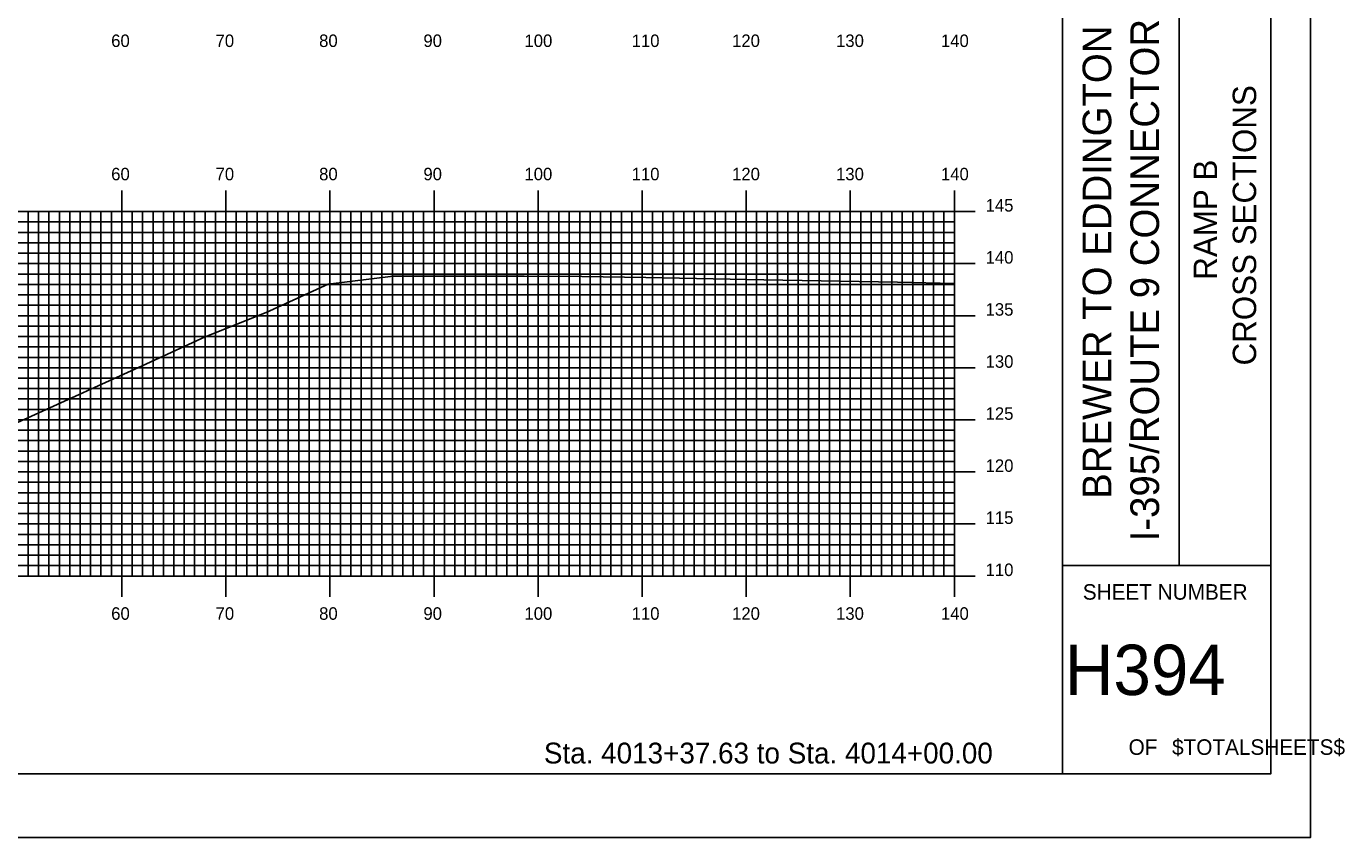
# Model space of a CAD drawing. Extents: x 853328 to 853671, y 364661 to 364881.
# Drawn here: x 853544.1 to 853670.8, y 364661.3 to 364739.1 of the extents above; entities that cross this region are included whole.
import ezdxf

# ---------------------------------------------------------------- set-up
doc = ezdxf.new("R2010")
doc.units = 0
for name, color, linetype in [('BORDER', 7, 'Continuous'), ('H_V ANNOTATION', 7, 'Continuous'), ('MAJOR', 7, 'Continuous'), ('MINOR', 7, 'Continuous'), ('PLOT BOUNDARY', 7, 'Continuous'), ('S_Roadway_Centerline', 7, 'Continuous')]:
    doc.layers.add(name, color=color, linetype=linetype)

msp = doc.modelspace()

# ---------------------------------------------------------------- linework, layer by layer
at = {"layer": 'BORDER'}
for p, q in [((853643.69, 364667.37), (853643.69, 364877.37)), ((853654.88, 364687.38), (853654.88, 364757.38)), ((853643.69, 364687.38), (853663.69, 364687.38))]:
    msp.add_line(p, q, dxfattribs=at)
msp.add_lwpolyline([(853343.69, 364667.37), (853663.69, 364667.37), (853663.69, 364877.37), (853343.69, 364877.37)], close=True, dxfattribs=at)
at = {"layer": 'MAJOR'}
for p, q in [((853553.29, 364723.38), (853553.29, 364721.37)), ((853563.29, 364723.38), (853563.29, 364721.37)), ((853573.29, 364723.38), (853573.29, 364721.37)), ((853583.29, 364723.38), (853583.29, 364721.37)), ((853593.29, 364723.38), (853593.29, 364721.37)), ((853603.29, 364723.38), (853603.29, 364721.37)), ((853613.29, 364723.38), (853613.29, 364721.37)), ((853623.29, 364723.38), (853623.29, 364721.37)), ((853633.29, 364723.38), (853633.29, 364721.37)), ((853353.29, 364721.37), (853633.29, 364721.37)), ((853353.29, 364721.37), (853633.29, 364721.37)), ((853553.29, 364686.37), (853553.29, 364721.37)), ((853563.29, 364686.37), (853563.29, 364721.37)), ((853573.29, 364686.37), (853573.29, 364721.37)), ((853583.29, 364686.37), (853583.29, 364721.37)), ((853593.29, 364686.37), (853593.29, 364721.37)), ((853603.29, 364686.37), (853603.29, 364721.37)), ((853613.29, 364686.37), (853613.29, 364721.37)), ((853623.29, 364686.37), (853623.29, 364721.37)), ((853635.3, 364721.37), (853631.29, 364721.37)), ((853633.29, 364686.37), (853633.29, 364721.37)), ((853633.29, 364686.37), (853633.29, 364721.37)), ((853353.29, 364716.37), (853633.29, 364716.37)), ((853635.3, 364716.37), (853631.29, 364716.37)), ((853353.29, 364711.37), (853633.29, 364711.37)), ((853635.3, 364711.37), (853631.29, 364711.37)), ((853353.29, 364706.37), (853633.29, 364706.37)), ((853635.3, 364706.37), (853631.29, 364706.37)), ((853353.29, 364701.37), (853633.29, 364701.37)), ((853635.3, 364701.37), (853631.29, 364701.37)), ((853353.29, 364696.37), (853633.29, 364696.37)), ((853635.3, 364696.37), (853631.29, 364696.37)), ((853353.29, 364691.37), (853633.29, 364691.37)), ((853635.3, 364691.37), (853631.29, 364691.37)), ((853353.29, 364686.37), (853633.29, 364686.37)), ((853353.29, 364686.37), (853633.29, 364686.37)), ((853553.29, 364684.37), (853553.29, 364686.37)), ((853563.29, 364684.37), (853563.29, 364686.37)), ((853573.29, 364684.37), (853573.29, 364686.37)), ((853583.29, 364684.37), (853583.29, 364686.37)), ((853593.29, 364684.37), (853593.29, 364686.37)), ((853603.29, 364684.37), (853603.29, 364686.37)), ((853613.29, 364684.37), (853613.29, 364686.37)), ((853623.29, 364684.37), (853623.29, 364686.37)), ((853635.3, 364686.37), (853631.29, 364686.37)), ((853633.29, 364684.37), (853633.29, 364686.37))]:
    msp.add_line(p, q, dxfattribs=at)
at = {"layer": 'MINOR'}
for p, q in [((853544.29, 364686.37), (853544.29, 364721.37)), ((853545.29, 364686.37), (853545.29, 364721.37)), ((853546.29, 364686.37), (853546.29, 364721.37)), ((853547.29, 364686.37), (853547.29, 364721.37)), ((853548.29, 364686.37), (853548.29, 364721.37)), ((853549.29, 364686.37), (853549.29, 364721.37)), ((853550.29, 364686.37), (853550.29, 364721.37)), ((853551.29, 364686.37), (853551.29, 364721.37)), ((853552.29, 364686.37), (853552.29, 364721.37)), ((853554.29, 364686.37), (853554.29, 364721.37)), ((853555.29, 364686.37), (853555.29, 364721.37)), ((853556.29, 364686.37), (853556.29, 364721.37)), ((853557.29, 364686.37), (853557.29, 364721.37)), ((853558.29, 364686.37), (853558.29, 364721.37)), ((853559.29, 364686.37), (853559.29, 364721.37)), ((853560.29, 364686.37), (853560.29, 364721.37)), ((853561.29, 364686.37), (853561.29, 364721.37)), ((853562.29, 364686.37), (853562.29, 364721.37)), ((853564.29, 364686.37), (853564.29, 364721.37)), ((853565.29, 364686.37), (853565.29, 364721.37)), ((853566.29, 364686.37), (853566.29, 364721.37)), ((853567.29, 364686.37), (853567.29, 364721.37)), ((853568.29, 364686.37), (853568.29, 364721.37)), ((853569.29, 364686.37), (853569.29, 364721.37)), ((853570.29, 364686.37), (853570.29, 364721.37)), ((853571.29, 364686.37), (853571.29, 364721.37)), ((853572.29, 364686.37), (853572.29, 364721.37)), ((853574.29, 364686.37), (853574.29, 364721.37)), ((853575.29, 364686.37), (853575.29, 364721.37)), ((853576.29, 364686.37), (853576.29, 364721.37)), ((853577.29, 364686.37), (853577.29, 364721.37)), ((853578.29, 364686.37), (853578.29, 364721.37)), ((853579.29, 364686.37), (853579.29, 364721.37)), ((853580.29, 364686.37), (853580.29, 364721.37)), ((853581.29, 364686.37), (853581.29, 364721.37)), ((853582.29, 364686.37), (853582.29, 364721.37)), ((853584.29, 364686.37), (853584.29, 364721.37)), ((853585.29, 364686.37), (853585.29, 364721.37)), ((853586.29, 364686.37), (853586.29, 364721.37)), ((853587.29, 364686.37), (853587.29, 364721.37)), ((853588.29, 364686.37), (853588.29, 364721.37)), ((853589.29, 364686.37), (853589.29, 364721.37)), ((853590.29, 364686.37), (853590.29, 364721.37)), ((853591.29, 364686.37), (853591.29, 364721.37)), ((853592.29, 364686.37), (853592.29, 364721.37)), ((853594.29, 364686.37), (853594.29, 364721.37)), ((853595.29, 364686.37), (853595.29, 364721.37)), ((853596.29, 364686.37), (853596.29, 364721.37)), ((853597.29, 364686.37), (853597.29, 364721.37)), ((853598.29, 364686.37), (853598.29, 364721.37)), ((853599.29, 364686.37), (853599.29, 364721.37)), ((853600.29, 364686.37), (853600.29, 364721.37)), ((853601.29, 364686.37), (853601.29, 364721.37)), ((853602.29, 364686.37), (853602.29, 364721.37)), ((853604.29, 364686.37), (853604.29, 364721.37)), ((853605.29, 364686.37), (853605.29, 364721.37)), ((853606.29, 364686.37), (853606.29, 364721.37)), ((853607.29, 364686.37), (853607.29, 364721.37)), ((853608.29, 364686.37), (853608.29, 364721.37)), ((853609.29, 364686.37), (853609.29, 364721.37)), ((853610.29, 364686.37), (853610.29, 364721.37)), ((853611.29, 364686.37), (853611.29, 364721.37)), ((853612.29, 364686.37), (853612.29, 364721.37)), ((853614.29, 364686.37), (853614.29, 364721.37)), ((853615.29, 364686.37), (853615.29, 364721.37)), ((853616.29, 364686.37), (853616.29, 364721.37)), ((853617.29, 364686.37), (853617.29, 364721.37)), ((853618.29, 364686.37), (853618.29, 364721.37)), ((853619.29, 364686.37), (853619.29, 364721.37)), ((853620.29, 364686.37), (853620.29, 364721.37)), ((853621.29, 364686.37), (853621.29, 364721.37)), ((853622.29, 364686.37), (853622.29, 364721.37)), ((853624.29, 364686.37), (853624.29, 364721.37)), ((853625.29, 364686.37), (853625.29, 364721.37)), ((853626.29, 364686.37), (853626.29, 364721.37)), ((853627.29, 364686.37), (853627.29, 364721.37)), ((853628.29, 364686.37), (853628.29, 364721.37)), ((853629.29, 364686.37), (853629.29, 364721.37)), ((853630.29, 364686.37), (853630.29, 364721.37)), ((853631.29, 364686.37), (853631.29, 364721.37)), ((853632.29, 364686.37), (853632.29, 364721.37)), ((853353.29, 364720.37), (853633.29, 364720.37)), ((853353.29, 364719.37), (853633.29, 364719.37)), ((853633.29, 364720.37), (853631.29, 364720.37)), ((853633.29, 364719.37), (853631.29, 364719.37)), ((853353.29, 364718.37), (853633.29, 364718.37)), ((853633.29, 364718.37), (853631.29, 364718.37)), ((853353.29, 364717.37), (853633.29, 364717.37)), ((853633.29, 364717.37), (853631.29, 364717.37)), ((853353.29, 364715.37), (853633.29, 364715.37)), ((853353.29, 364714.37), (853633.29, 364714.37)), ((853633.29, 364715.37), (853631.29, 364715.37)), ((853633.29, 364714.37), (853631.29, 364714.37)), ((853353.29, 364713.37), (853633.29, 364713.37)), ((853633.29, 364713.37), (853631.29, 364713.37)), ((853353.29, 364712.37), (853633.29, 364712.37)), ((853633.29, 364712.37), (853631.29, 364712.37)), ((853353.29, 364710.37), (853633.29, 364710.37)), ((853353.29, 364709.37), (853633.29, 364709.37)), ((853633.29, 364710.37), (853631.29, 364710.37)), ((853633.29, 364709.37), (853631.29, 364709.37)), ((853353.29, 364708.37), (853633.29, 364708.37)), ((853633.29, 364708.37), (853631.29, 364708.37)), ((853353.29, 364707.37), (853633.29, 364707.37)), ((853633.29, 364707.37), (853631.29, 364707.37)), ((853353.29, 364705.37), (853633.29, 364705.37)), ((853353.29, 364704.37), (853633.29, 364704.37)), ((853633.29, 364705.37), (853631.29, 364705.37)), ((853633.29, 364704.37), (853631.29, 364704.37)), ((853353.29, 364703.37), (853633.29, 364703.37)), ((853633.29, 364703.37), (853631.29, 364703.37)), ((853353.29, 364702.37), (853633.29, 364702.37)), ((853633.29, 364702.37), (853631.29, 364702.37)), ((853353.29, 364700.37), (853633.29, 364700.37)), ((853633.29, 364700.37), (853631.29, 364700.37)), ((853353.29, 364699.37), (853633.29, 364699.37)), ((853633.29, 364699.37), (853631.29, 364699.37)), ((853353.29, 364698.37), (853633.29, 364698.37)), ((853633.29, 364698.37), (853631.29, 364698.37)), ((853353.29, 364697.37), (853633.29, 364697.37)), ((853633.29, 364697.37), (853631.29, 364697.37)), ((853353.29, 364695.37), (853633.29, 364695.37)), ((853633.29, 364695.37), (853631.29, 364695.37)), ((853353.29, 364694.37), (853633.29, 364694.37)), ((853633.29, 364694.37), (853631.29, 364694.37)), ((853353.29, 364693.37), (853633.29, 364693.37)), ((853633.29, 364693.37), (853631.29, 364693.37)), ((853353.29, 364692.37), (853633.29, 364692.37)), ((853633.29, 364692.37), (853631.29, 364692.37)), ((853353.29, 364690.37), (853633.29, 364690.37)), ((853633.29, 364690.37), (853631.29, 364690.37)), ((853353.29, 364689.37), (853633.29, 364689.37)), ((853633.29, 364689.37), (853631.29, 364689.37)), ((853353.29, 364688.37), (853633.29, 364688.37)), ((853633.29, 364688.37), (853631.29, 364688.37)), ((853353.29, 364687.37), (853633.29, 364687.37)), ((853633.29, 364687.37), (853631.29, 364687.37))]:
    msp.add_line(p, q, dxfattribs=at)
at = {"layer": 'PLOT BOUNDARY'}
msp.add_lwpolyline([(853327.51, 364661.25), (853667.51, 364661.25), (853667.51, 364881.25), (853327.51, 364881.25)], close=True, dxfattribs=at)
at = {"layer": 'S_Roadway_Centerline'}
msp.add_lwpolyline([(853538.04, 364698.79), (853544.25, 364701.55), (853555.25, 364706.56), (853561.3, 364709.33), (853567.17, 364711.68), (853573.12, 364714.41), (853579.38, 364715.18), (853591.96, 364715.17), (853597.51, 364715.12), (853603.64, 364715.04), (853614.97, 364714.82), (853627.83, 364714.6), (853633.29, 364714.45)], dxfattribs=at)

# ---------------------------------------------------------------- texts
at = {"layer": 'BORDER'}
for s, height, p in [('I-395/ROUTE 9 CONNECTOR', 2.7557, (853652.96, 364689.7)), ('BREWER TO EDDINGTON', 2.7557, (853648.37, 364693.78)), ('CROSS SECTIONS', 2.25, (853662.29, 364706.59)), ('RAMP B', 2.25, (853658.54, 364714.82))]:
    msp.add_text(s, height=height, rotation=90, dxfattribs=at).set_placement(p)
for s, height, p in [('SHEET NUMBER', 1.4905, (853645.63, 364684.1)), ('H394', 4.839, (853643.9, 364674.94)), ('OF', 1.491, (853650.03, 364669.2)), ('$TOTALSHEETS$', 1.4905, (853654.21, 364669.2))]:
    msp.add_text(s, height=height, dxfattribs=at).set_placement(p)
at = {"layer": 'H_V ANNOTATION'}
for s, height, p in [('60', 1.2, (853552.27, 364737.17)), ('70', 1.2, (853562.3, 364737.17)), ('80', 1.2, (853572.25, 364737.17)), ('90', 1.2, (853582.27, 364737.17)), ('100', 1.2, (853591.98, 364737.17)), ('110', 1.2, (853602.28, 364737.17)), ('120', 1.2, (853611.93, 364737.17)), ('130', 1.2, (853621.92, 364737.17)), ('140', 1.2, (853632, 364737.17)), ('60', 1.2, (853552.27, 364724.37)), ('70', 1.2, (853562.3, 364724.37)), ('80', 1.2, (853572.25, 364724.37)), ('90', 1.2, (853582.27, 364724.37)), ('100', 1.2, (853591.98, 364724.37)), ('110', 1.2, (853602.28, 364724.37)), ('120', 1.2, (853611.93, 364724.37)), ('130', 1.2, (853621.92, 364724.37)), ('140', 1.2, (853632, 364724.37)), ('145', 1.2, (853636.29, 364721.37)), ('140', 1.2, (853636.29, 364716.37)), ('135', 1.2, (853636.29, 364711.37)), ('130', 1.2, (853636.29, 364706.37)), ('125', 1.2, (853636.29, 364701.37)), ('120', 1.2, (853636.29, 364696.37)), ('115', 1.2, (853636.29, 364691.37)), ('110', 1.2, (853636.29, 364686.37)), ('60', 1.2, (853552.27, 364682.17)), ('70', 1.2, (853562.3, 364682.17)), ('80', 1.2, (853572.25, 364682.17)), ('90', 1.2, (853582.27, 364682.17)), ('100', 1.2, (853591.98, 364682.17)), ('110', 1.2, (853602.28, 364682.17)), ('120', 1.2, (853611.93, 364682.17)), ('130', 1.2, (853621.92, 364682.17)), ('140', 1.2, (853632, 364682.17)), ('Sta. 4013+37.63 to Sta. 4014+00.00', 2.0004, (853593.85, 364668.37))]:
    msp.add_text(s, height=height, dxfattribs=at).set_placement(p)

doc.saveas('drawing.dxf')
